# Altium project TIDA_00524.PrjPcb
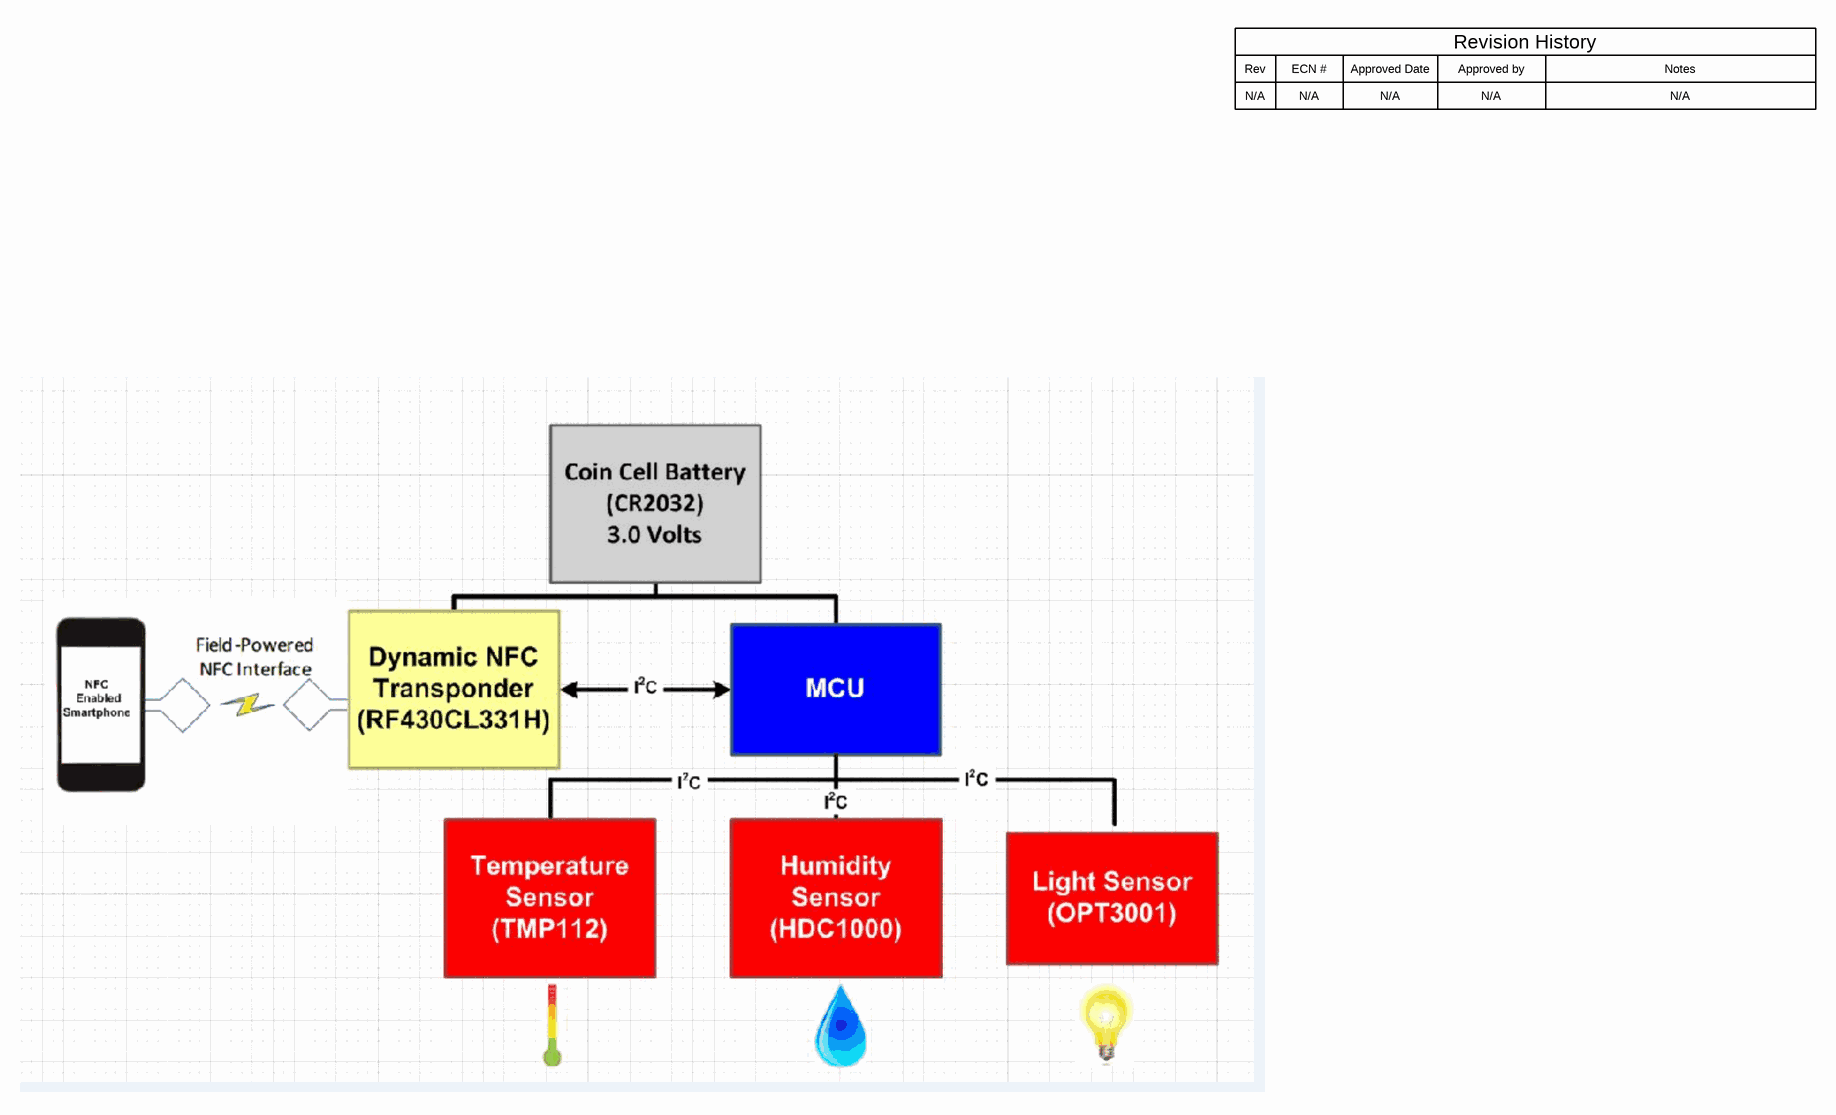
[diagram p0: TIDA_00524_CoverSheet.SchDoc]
CopyrightYear: 2015; PCB_Layout: Eddie LaCost; PCB_Rev: A; PRJ_Customer: Public Release; PRJ_Engineer: Eddie LaCost; PRJ_Number: TIDA-00524; PRJ_Title: NFC-DATALOGGER-EVM; SCH_Rev: A; TechSupport: http://www.ti.com/support; TID: TIDA-00524
3 sheets, 55 parts. Net scope: global (net labels, ports and power ports of the same name join across sheets).
Board file: TIDA00524.PcbDoc
Sheets:
  TIDA_00524_CoverSheet.SchDoc
  TIDA_00524.SchDoc
  TIDA00524_Hardware.SchDoc

## Sheet TIDA_00524_CoverSheet.SchDoc
size 431 x 279 mm; Date: Not shown in title block; ApprovedBy: Not shown in title block; CheckedBy: Not shown in title block; Author: Not shown in title block; CompanyName: Not shown in title block; Engineer: Not shown in title block; Organization: Not shown in title block; Address1: Not shown in title block; Address2: Not shown in title block; Address3: Not shown in title block; Address4: Not shown in title block; DocumentNumber: 1; Revision: Use project parameter SCH_Rev; SheetNumber: 1; SheetTotal: 3; PageSetup: Record=PageOptions¦CenterHorizontal=True¦CenterVertical=True¦PrintScale=1.00¦XCorrection=1.00¦YCorrection=1.00¦PrintKind=0¦BorderSize=5000000¦LeftOffset=0¦BottomOffset=0¦Orientation=2¦PaperLength=1000¦PaperWidth=1000¦Scale=100¦PaperSource=15¦PrintQuality=600¦MediaType=1¦DitherType=10¦PaperKind=Letter¦PrintScaleMode=1

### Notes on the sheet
- Rev
- N/A
- ECN #
- Approved Date
- Approved by
- Revision History
- Notes
- Place Block Diagram here (if appropriate) or delete this text box.
  If using a block diagram from another tool, save the picture as a .bmp file.
  Then, use menu Place|Drawing Tools|Graphic to insert the .png/.svg/.bmp file on the schematic.

## Sheet TIDA_00524.SchDoc
size 431 x 279 mm; Date: Not shown in title block; ApprovedBy: Not shown in title block; CheckedBy: Not shown in title block; Author: Not shown in title block; CompanyName: Not shown in title block; Engineer: Not shown in title block; Organization: Not shown in title block; Address1: Not shown in title block; Address2: Not shown in title block; Address3: Not shown in title block; Address4: Not shown in title block; DocumentNumber: 1; Revision: Use project parameter SCH_Rev; SheetNumber: 2; SheetTotal: 3; PageSetup: Record=PageOptions¦CenterHorizontal=True¦CenterVertical=True¦PrintScale=1.00¦XCorrection=1.00¦YCorrection=1.00¦PrintKind=0¦BorderSize=5000000¦LeftOffset=0¦BottomOffset=0¦Orientation=2¦PaperLength=1000¦PaperWidth=1000¦Scale=100¦PaperSource=15¦PrintQuality=600¦MediaType=1¦DitherType=10¦PaperKind=Letter¦PrintScaleMode=1
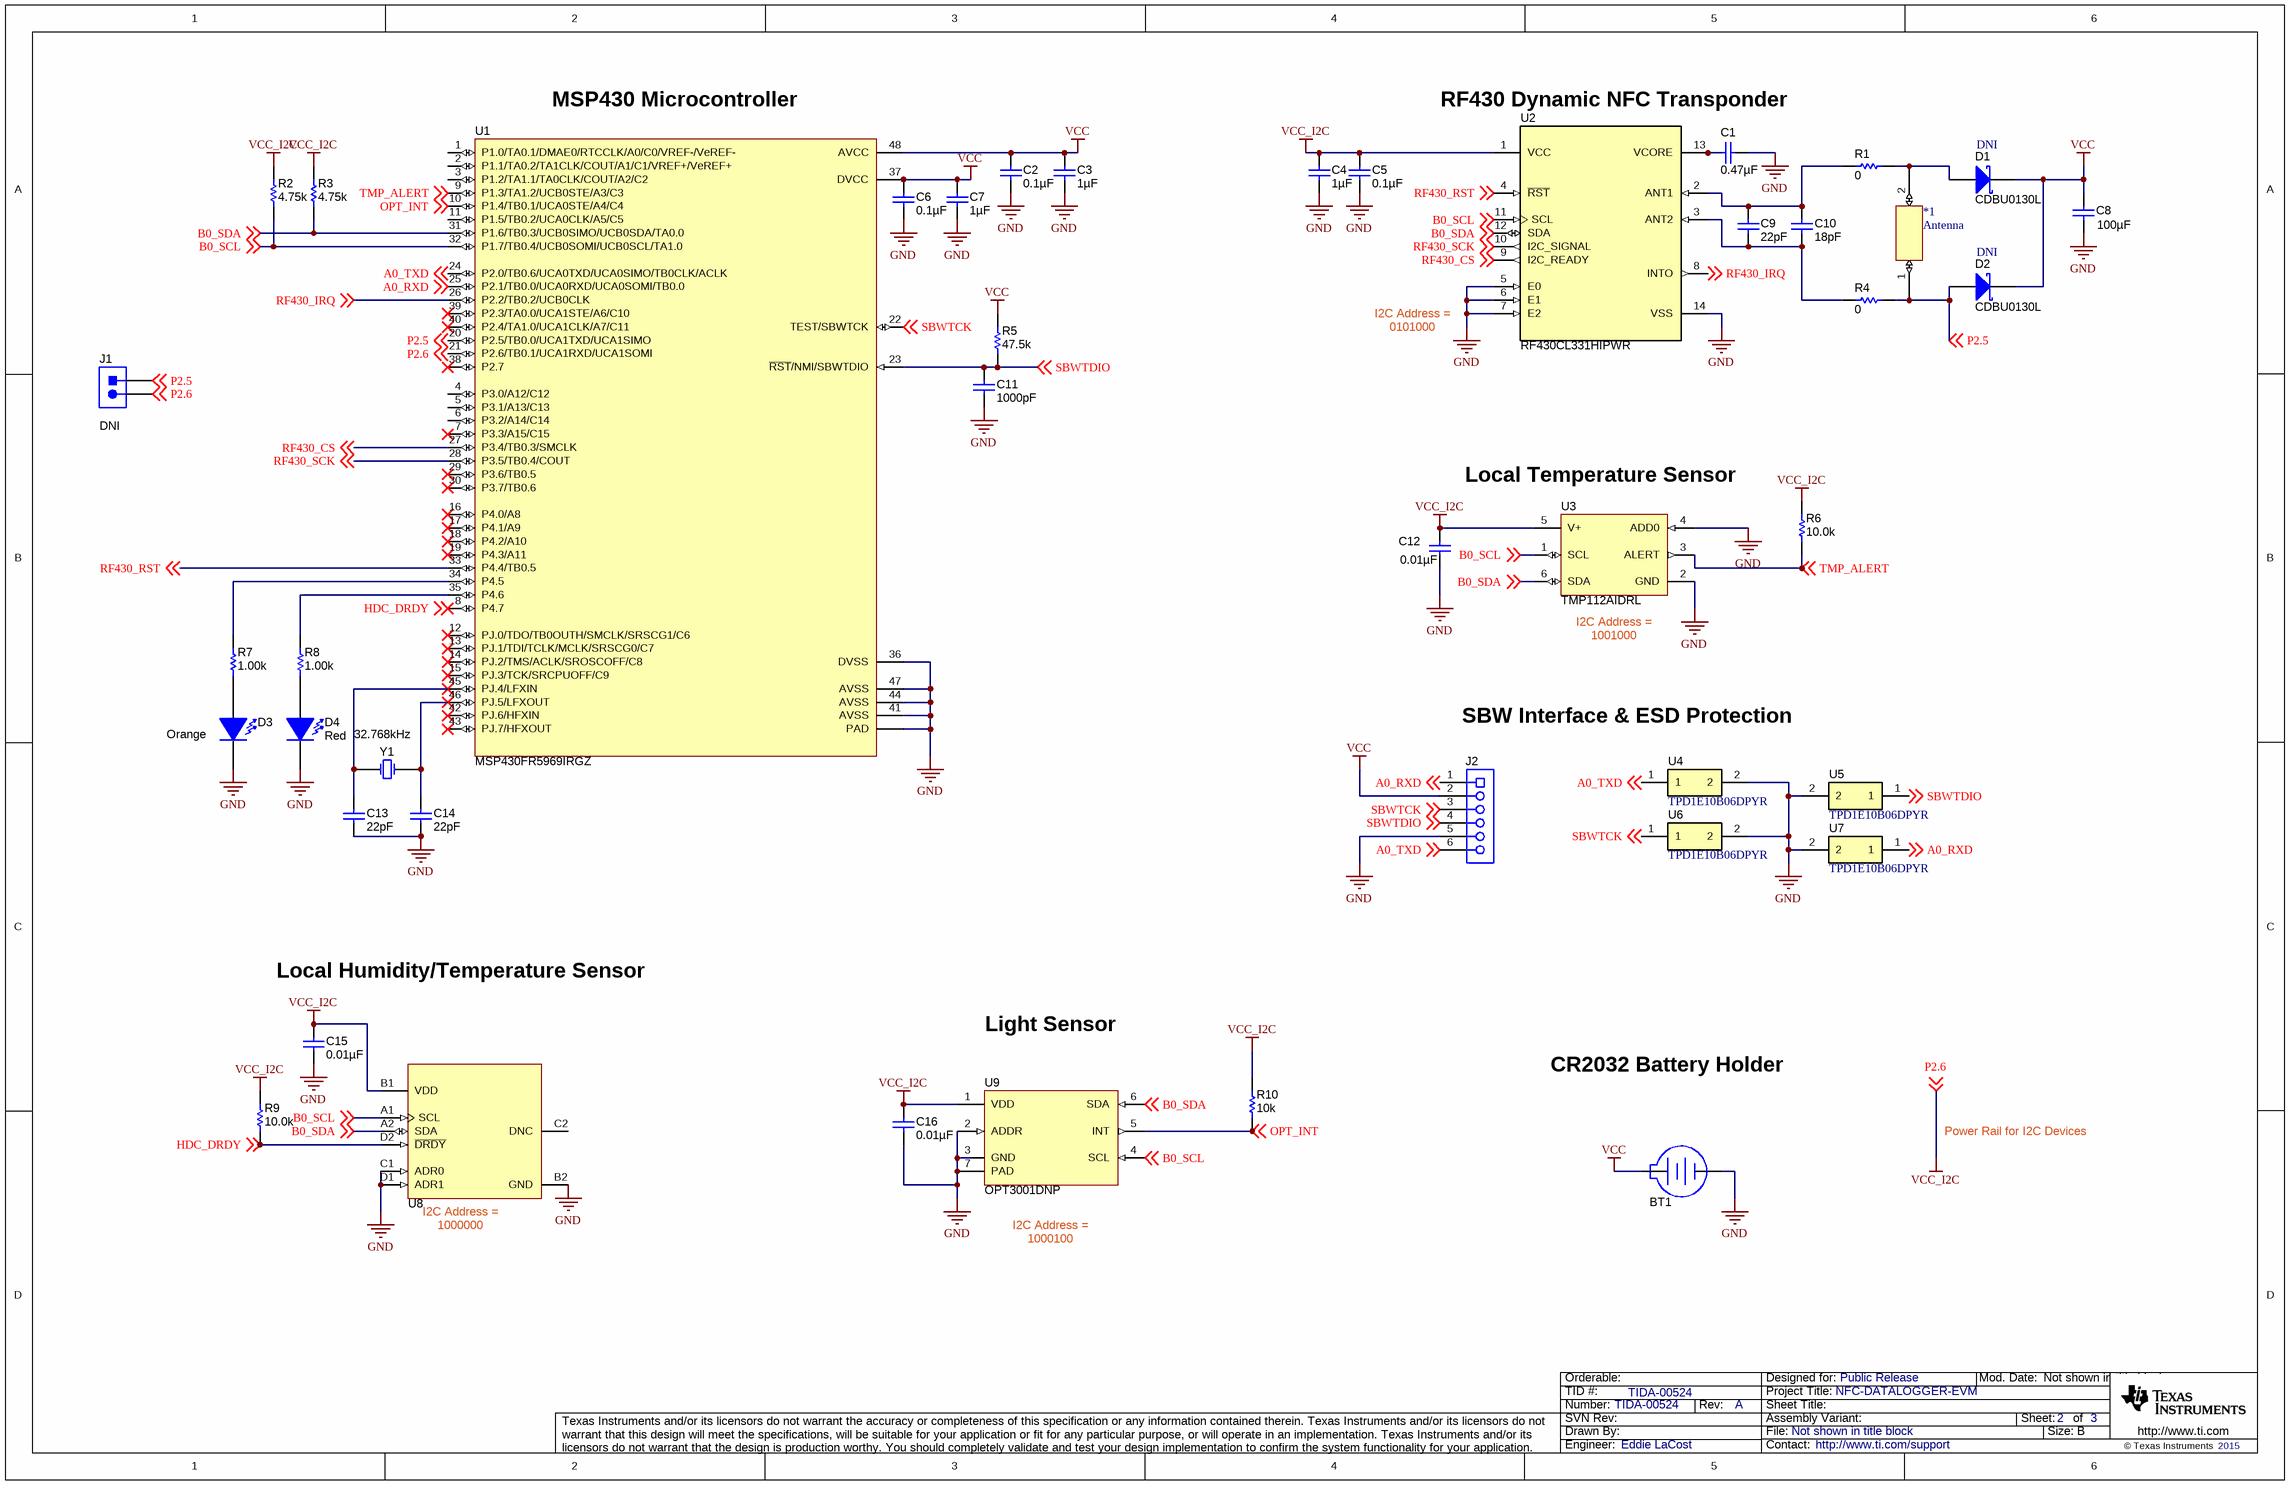
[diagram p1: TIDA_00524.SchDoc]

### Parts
*1  Antenna  [PCBComponent_1]  (no BOM)
BT1  BA2032SM  [BAT_BA2032SM]  (value not drawn)
C1  ValueDisplayed: 0.47µF  [0603]  (hidden comment: GRM188R71E474KA12D)
C2  ValueDisplayed: 0.1µF  [0402]  (hidden comment: GRM155R71C104KA88D)
C3  ValueDisplayed: 1µF  [0603]  (hidden comment: GRM188R71C105KA12D)
C4  ValueDisplayed: 1µF  [0603]  (hidden comment: GRM188R71C105KA12D)
C5  ValueDisplayed: 0.1µF  [0402]  (hidden comment: GRM155R71C104KA88D)
C6  ValueDisplayed: 0.1µF  [0402]  (hidden comment: GRM155R71C104KA88D)
C7  ValueDisplayed: 1µF  [0603]  (hidden comment: GRM188R71C105KA12D)
C8  ValueDisplayed: 100µF  [1206_190]  (hidden comment: C3216X5R1A107M160AC)
C9  ValueDisplayed: 22pF  [0402]  (hidden comment: GRM1555C1H220FA01D)
C10  ValueDisplayed: 18pF  [0402]  (hidden comment: GRM1555C1H180JA01D)
C11  ValueDisplayed: 1000pF  [0402]  (hidden comment: GRM155R71C102KA01D)
C12  ValueDisplayed: 0.01µF  [0402]  (hidden comment: GRM155R71C103KA01D)
C13  ValueDisplayed: 22pF  [0402]  (hidden comment: GRM1555C1H220FA01D)
C14  ValueDisplayed: 22pF  [0402]  (hidden comment: GRM1555C1H220FA01D)
C15  ValueDisplayed: 0.01µF  [0402]  (hidden comment: C1005X7R1E103K)
C16  ValueDisplayed: 0.01µF  [0402]  (hidden comment: 885012205031)
D1  CDBU0130L  [SOD-523F]
D2  CDBU0130L  [SOD-523F]
D3  value Orange  [SML-31_Orange]  (hidden comment: SML-311DTT86)
D4  value Red  [SML-31_Red]  (hidden comment: SML-311UTT86)
J1  GRPB021VWVN-RC  [Sullins_GRPB021VWVN-RC]  (value not drawn)
J2  851-43-006-10-001000  [Mill-Max_851-XX-006-10-001000]  (value not drawn)
R1  value 0  [0402]  (hidden comment: CRCW04020000Z0ED)
R2  value 4.75k  [0402]  (hidden comment: CRCW04024K75FKED)
R3  value 4.75k  [0402]  (hidden comment: CRCW04024K75FKED)
R4  value 0  [0402]  (hidden comment: CRCW04020000Z0ED)
R5  value 47.5k  [0402]  (hidden comment: CRCW040247K5FKED)
R6  ValueDisplayed: 10.0k  [0402]  (hidden comment: CRCW040210K0FKED)
R7  value 1.00k  [0402]  (hidden comment: CRCW04021K00FKED)
R8  value 1.00k  [0402]  (hidden comment: CRCW04021K00FKED)
R9  ValueDisplayed: 10.0k  [0402]  (hidden comment: CRCW040210K0FKED)
R10  ValueDisplayed: 10k  [0402]  (hidden comment: CRCW040210K0JNED)
U1  MSP430FR5969IRGZ  [RGZ0048B]
U2  RF430CL331HIPWR  [PW0014A_N]
U3  TMP112AIDRL  [DRL0006A]
U4  TPD1E10B06DPYR  [DPY0002A]
U5  TPD1E10B06DPYR  [DPY0002A]
U6  TPD1E10B06DPYR  [DPY0002A]
U7  TPD1E10B06DPYR  [DPY0002A]
U8  HDC1000YPAR  [YPA0008AGAE]  (value not drawn)
U9  OPT3001DNP  [DNP0006A]
Y1  Frequency: 32.768kHz  [XTAL_ABS07]  (hidden comment: ABS07-32.768KHZ-9-T)

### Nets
GND: BT1.2(-) C1.2 C2.2 C3.2 C4.2 C5.2 C6.2 C7.2 C8.2 C11.2 C12.1 C13.2 C14.2 C15.2 C16.2 D3.1(K) D4.1(K) J2.5 U1.36(DVSS) U1.41(AVSS) U1.44(AVSS) U1.47(AVSS) U1.49(PAD) U2.5(E0) U2.6(E1) U2.7(E2) U2.14(VSS) U3.2(GND) U3.4(ADD0) U4.2 U5.2 U6.2 U7.2 U8.B2(GND) U8.C1(ADR0) U8.D1(ADR1) U9.2(ADDR) U9.3(GND) U9.7(PAD)
VCC: BT1.1(+) C2.1 C3.1 C6.1 C7.1 C8.1 D1.1(K) D2.1(K) J2.2 R5.2 U1.37(DVCC) U1.48(AVCC)
VCC_I2C: C4.1 C5.1 C12.2 C15.1 C16.1 J1.2 R2.2 R3.2 R6.2 R9.1 R10.2 U1.21(P2.6/TB0.1/UCA1RXD/UCA1SOMI) U2.1(VCC) U3.5(V+) U8.B1(VDD) U9.1(VDD) ; off-sheet P2.6  [also labelled P2.6]
A0_RXD: J2.1 U1.25(P2.1/TB0.0/UCA0RXD/UCA0SOMI/TB0.0) U7.1 ; off-sheet A0_RXD
A0_TXD: J2.6 U1.24(P2.0/TB0.6/UCA0TXD/UCA0SIMO/TB0CLK/ACLK) U4.1 ; off-sheet A0_TXD
B0_SCL: R2.1 U1.32(P1.7/TB0.4/UCB0SOMI/UCB0SCL/TA1.0) U2.11(SCL) U3.1(SCL) U8.A1(SCL) U9.4(SCL) ; off-sheet B0_SCL
B0_SDA: R3.1 U1.31(P1.6/TB0.3/UCB0SIMO/UCB0SDA/TA0.0) U2.12(SDA) U3.6(SDA) U8.A2(SDA) U9.6(SDA) ; off-sheet B0_SDA
HDC_DRDY: R9.2 U1.8(P4.7) U8.D2(~{DRDY}) ; off-sheet HDC_DRDY
OPT_INT: R10.1 U1.10(P1.4/TB0.1/UCA0STE/A4/C4) U9.5(INT) ; off-sheet OPT_INT
P2.5: *1.1 D2.2(A) J1.1 R4.2 U1.20(P2.5/TB0.0/UCA1TXD/UCA1SIMO) ; off-sheet P2.5
RF430_CS: U1.27(P3.4/TB0.3/SMCLK) U2.9(I2C_READY) ; off-sheet RF430_CS
RF430_IRQ: U1.26(P2.2/TB0.2/UCB0CLK) U2.8(INTO) ; off-sheet RF430_IRQ
RF430_RST: U1.33(P4.4/TB0.5) U2.4(~{RST}) ; off-sheet RF430_RST
RF430_SCK: U1.28(P3.5/TB0.4/COUT) U2.10(I2C_SIGNAL) ; off-sheet RF430_SCK
SBWTCK: J2.3 U1.22(TEST/SBWTCK) U6.1 ; off-sheet SBWTCK
SBWTDIO: C11.1 J2.4 R5.1 U1.23(~{RST}/NMI/SBWTDIO) U5.1 ; off-sheet SBWTDIO
TMP_ALERT: R6.1 U1.9(P1.3/TA1.2/UCB0STE/A3/C3) U3.3(ALERT) ; off-sheet TMP_ALERT
Net*1_2: *1.2 D1.2(A) R1.2
NetC1_1: C1.1 U2.13(VCORE)
NetC9_1: C9.1 C10.1 R1.1 U2.2(ANT1)
NetC9_2: C9.2 C10.2 R4.1 U2.3(ANT2)
NetC13_1: C13.1 U1.45(PJ.4/LFXIN) Y1.2(OSC2)
NetC14_1: C14.1 U1.46(PJ.5/LFXOUT) Y1.1(OSC1)
NetD3_2: D3.2(A) R7.1
NetD4_2: D4.2(A) R8.1
NetR7_2: R7.2 U1.34(P4.5)
NetR8_2: R8.2 U1.35(P4.6)

Not connected (* = marked no-connect by the designer): U1 1(P1.0/TA0.1/DMAE0/RTCCLK/A0/C0/VREF-/VeREF-) 2(P1.1/TA0.2/TA1CLK/COUT/A1/C1/VREF+/VeREF+) 3(P1.2/TA1.1/TA0CLK/COUT/A2/C2) 4(P3.0/A12/C12) 5(P3.1/A13/C13) 6(P3.2/A14/C14) 7(P3.3/A15/C15)* 11(P1.5/TB0.2/UCA0CLK/A5/C5) 12(PJ.0/TDO/TB0OUTH/SMCLK/SRSCG1/C6)* 13(PJ.1/TDI/TCLK/MCLK/SRSCG0/C7)* 14(PJ.2/TMS/ACLK/SROSCOFF/C8)* 15(PJ.3/TCK/SRCPUOFF/C9)* 16(P4.0/A8)* 17(P4.1/A9)* 18(P4.2/A10)* 19(P4.3/A11)* 29(P3.6/TB0.5)* 30(P3.7/TB0.6)* 38(P2.7)* 39(P2.3/TA0.0/UCA1STE/A6/C10)* 40(P2.4/TA1.0/UCA1CLK/A7/C11)* 42(PJ.6/HFXIN)* 43(PJ.7/HFXOUT)*; U8 C2(DNC)

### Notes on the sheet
- (near U1) MSP430 Microcontroller
- RF430 Dynamic NFC Transponder
- (near D1) DNI
- (near D2) DNI
- I2C Address =
- 0101000
- Local Temperature Sensor
- (near U3) I2C Address =
- (near U3) 1001000
- SBW Interface & ESD Protection
- Local Humidity/Temperature Sensor
- Light Sensor
- CR2032 Battery Holder
- Power Rail for I2C Devices
- (near U8) I2C Address =
- (near U8) 1000000
- (near U9) I2C Address =
- 1000100

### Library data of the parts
*1 = Component_1
BT1 = BA2032SM: Battery Holder,xx 2032 series, 20mm Dia, SMT; Manufacturer: Memory Protection Devices; SymbolCreator: a0412235
C1 = GRM188R71E474KA12D: CAP, CERM, 0.47 µF, 25 V, +/- 10%, X7R, 0603; Manufacturer: MuRata; Polarized: N; CompType: Capacitor; Value: 0.47uF; U/M: EA; Cap_F: 0.00000047; Tolerance_%: 10; Value1: Unknown; VDC_V: 25; Value2: 25V; TaMin_C: -55; TaMax_C: 125; AEC Category: Q200
C2 C5 C6 = GRM155R71C104KA88D: CAP, CERM, 0.1 µF, 16 V, +/- 10%, X7R, 0402; Manufacturer: MuRata; Polarized: N; CompType: Capacitor; Value: 0.1uF; U/M: EA; Cap_F: 0.0000001; Tolerance_%: 10; Value1: Unknown; VDC_V: 16; Value2: 16V; TaMin_C: -55; TaMax_C: 125; AEC Category: Q200
C3 C4 C7 = GRM188R71C105KA12D: CAP, CERM, 1 µF, 16 V, +/- 10%, X7R, 0603; Manufacturer: MuRata; Polarized: N; CompType: Capacitor; Value: 1uF; U/M: EA; Cap_F: 0.000001; Tolerance_%: 10; ESR_ohm: 0.011; Value1: 0.011 ohm; VDC_V: 16; Value2: 16V; TaMin_C: -55; TaMax_C: 125; AEC Category: Q200
C8 = C3216X5R1A107M160AC: CAP, CERM, 100 µF, 10 V, +/- 20%, X5R, 1206_190; Manufacturer: TDK; Polarized: N; CompType: Capacitor; Value: 100uF; U/M: EA; Cap_F: 0.0001; Tolerance_%: 20; Value1: Unknown; VDC_V: 10; Value2: 10V; TaMin_C: -55; TaMax_C: 85; Cap_Case: 1206; AEC Category: Q200
C9 = GRM1555C1H220FA01D: CAP, CERM, 22 pF, 50 V, +/- 1%, C0G/NP0, 0402; Manufacturer: MuRata; Polarized: N; CompType: Capacitor; U/M: EA; Cap_F: 0.000000000022; Tolerance_%: 1; Value1: Unknown; VDC_V: 50; Value2: 50V; TaMin_C: -55; TaMax_C: 125; Value: 22pF; AEC Category: Q200
C10 = GRM1555C1H180JA01D: CAP, CERM, 18 pF, 50 V, +/- 5%, C0G/NP0, 0402; Manufacturer: MuRata; Polarized: N; CompType: Capacitor; Value: 18pF; U/M: EA; Cap_F: 0.000000000018; Tolerance_%: 5; Value1: Unknown; VDC_V: 50; Value2: 50V; TaMin_C: -55; TaMax_C: 125; AEC Category: Q200
C11 = GRM155R71C102KA01D: CAP, CERM, 1000 pF, 16 V, +/- 10%, X7R, 0402; Manufacturer: MuRata; Polarized: N; CompType: Capacitor; Value: 1000pF; U/M: EA; Cap_F: 0.000000001; Tolerance_%: 10; Value1: Unknown; VDC_V: 16; Value2: 16V; TaMin_C: -55; TaMax_C: 125; AEC Category: Q200
C12 = GRM155R71C103KA01D: CAP, CERM, 0.01 µF, 16 V, +/- 10%, X7R, 0402; Manufacturer: MuRata; Polarized: N; CompType: Capacitor; Value: 0.01uF; U/M: EA; Cap_F: 0.00000001; Tolerance_%: 10; Value1: Unknown; VDC_V: 16; Value2: 16V; TaMin_C: -55; TaMax_C: 125; AEC Category: Q200
C13 C14 = GRM1555C1H220FA01D: CAP, CERM, 22 pF, 50 V, +/- 1%, C0G/NP0, 0402; Manufacturer: MuRata; Polarized: N; CompType: Capacitor; Value: 22pF; U/M: EA; Cap_F: 0.000000000022; Tolerance_%: 1; Value1: Unknown; VDC_V: 50; Value2: 50V; TaMin_C: -55; TaMax_C: 125; AEC Category: Q200
C15 = C1005X7R1E103K: CAP, CERM, 0.01 µF, 25 V, +/- 10%, X7R, 0402; Manufacturer: TDK; Polarized: N; CompType: Capacitor; Value: 0.01uF; U/M: EA; Cap_F: 0.00000001; Tolerance_%: 10; ESR_ohm: 0.0623; Value1: 0.0623 ohm; VDC_V: 25; Value2: 25V; TaMin_C: -55; TaMax_C: 125; AEC Category: Q200
C16 = 885012205031: CAP, CERM, 0.01 µF, 16 V, +/- 10%, X7R, 0402; Manufacturer: Wurth Elektronik; Polarized: N; CompType: Capacitor; Value: 0.01uF; U/M: EA; Cap_F: 0.00000001; Tolerance_%: 10; Value1: Unknown; VDC_V: 16; Value2: 16V; TaMin_C: -55; TaMax_C: 125; AEC Category: Q200
D1 D2 = CDBU0130L: Diode, Schottky, 35 V, 0.1 A, SOD-523F; Manufacturer: Comchip Technology; U/M: EA; Value: 35V; Value1: 0.1A; Io_A: 0.1; Vr_V: 35; TJmax_C: 125; AEC Category: Q101
D3 = SML-311DTT86: LED, Orange, SMD; Manufacturer: Rohm; Type: AlInGaP; Vf_V: 1.8; Value2: 1.8V; Io_A: 0.002; Value1: W; U/M: EA
D4 = SML-311UTT86: LED, Red, SMD; Manufacturer: Rohm; Type: AlInGaP; Vf_V: 1.8; Value2: 1.8V; Io_A: 0.002; Value1: W; U/M: EA
J1 = GRPB021VWVN-RC: Header male, 2x1, 50mil, TH; Manufacturer: Sullins Connector Solutions; SymbolCreator: a0412235; U/M: EA
J2 = 851-43-006-10-001000: Receptacle, 6x1, 50mil, TH; Manufacturer: Mill-Max; SymbolCreator: a0411947; U/M: EA
R1 R4 = CRCW04020000Z0ED: RES, 0, 5%, 0.063 W, 0402; Manufacturer: Vishay-Dale; CompType: Resistor; Value_Code: 0000; Tolerance_%: 5; Power_W: 0.063; Value2: 0.063W; VDC_V: 50; TempCo: 200 ppm/C; EIA_Code: E24; U/M: EA; AEC Category: Q200
R2 R3 = CRCW04024K75FKED: RES, 4.75 k, 1%, 0.063 W, 0402; Manufacturer: Vishay-Dale; CompType: Resistor; Res_ohm: 4750; Value_Code: 4k75; Tolerance_%: 1; Power_W: 0.063; Value2: 0.063W; VDC_V: 50; TempCo: 100 ppm/C; EIA_Code: E96; U/M: EA; AEC Category: Q200
R5 = CRCW040247K5FKED: RES, 47.5 k, 1%, 0.063 W, 0402; Manufacturer: Vishay-Dale; CompType: Resistor; Res_ohm: 47500; Value_Code: 47k5; Tolerance_%: 1; Power_W: 0.063; Value2: 0.063W; VDC_V: 50; TempCo: 100 ppm/C; EIA_Code: E96; U/M: EA; AEC Category: Q200
R6 R9 = CRCW040210K0FKED: RES, 10.0 k, 1%, 0.063 W, 0402; Manufacturer: Vishay-Dale; CompType: Resistor; Value: 10.0k; U/M: EA; Res_ohm: 10000; Value_Code: 10k0; Tolerance_%: 1; Power_W: 0.063; Value2: 0.063W; VDC_V: 50; TempCo: 100 ppm/C; EIA_Code: E96; AEC Category: Q200
R7 R8 = CRCW04021K00FKED: RES, 1.00 k, 1%, 0.063 W, 0402; Manufacturer: Vishay-Dale; CompType: Resistor; Res_ohm: 1000; Value_Code: 1k00; Tolerance_%: 1; Power_W: 0.063; Value2: 0.063W; VDC_V: 50; TempCo: 100 ppm/C; EIA_Code: E96; U/M: EA; AEC Category: Q200
R10 = CRCW040210K0JNED: RES, 10 k, 5%, 0.063 W, 0402; Manufacturer: Vishay-Dale; CompType: Resistor; Value: 10k; U/M: EA; Res_ohm: 10000; Value_Code: 10k0; Tolerance_%: 5; Power_W: 0.063; Value2: 0.063W; VDC_V: 50; TempCo: 200 ppm/C; EIA_Code: E24; AEC Category: Q200
U1 = MSP430FR5969IRGZ: Mixed Signal Microcontroller, RGZ0048B; Alternate Manufacturer: None; Manufacturer: Texas Instruments; SymbolCreator: a0411947; CompType: IC; U/M: EA
U2 = RF430CL331HIPWR: NFC Type 4B Dynamic Dual Interface Transponder, PW0014A; Manufacturer: Texas Instruments; SymbolCreator: Altium; CompType: IC; U/M: EA
U3 = TMP112AIDRL: High-Accuracy, Low-Power, Digital Temperature Sensor With SMBus(TM)/Two-Wire Serial Interface, DRL0006A; Alternate Manufacturer: None; Manufacturer: Texas Instruments; SymbolCreator: a0799628; CompType: IC; U/M: EA
U4-U7 = TPD1E10B06DPYR: ESD in 0402 Package with 10 pF Capacitance and 6 V Breakdown, 1 Channel, -40 to +125 degC, 2-pin X2SON (DPY), Green (RoHS & no Sb/Br); Manufacturer: Texas Instruments; Alternate PartNumber: Equivalent; Breakdown Voltage(Min)(V): 6; Eco-Plan: TBD; IEC 61000-4-2 Air-Gap(+/- kV): 30; IO Capacitance(Typ)(pF): 10; SubFamily: ESD Solution
U8 = HDC1000YPAR: HDC1000 Low power integrated humidity and temperature Sensor, YPA0008AGAE; Alternate Manufacturer: Texas Instruments; Alternate PartNumber: HDC1000YPAT; SymbolCreator: Altium; CompType: IC; U/M: EA
U9 = OPT3001DNP: Ambient Light Sensor, DNP0006A; Alternate Manufacturer: None; Manufacturer: Texas Instruments; SymbolCreator: a0411947; CompType: IC; U/M: EA
Y1 = ABS07-32.768KHZ-9-T: CRYSTAL, 32.768KHZ, 9PF, SMD; Manufacturer: Abracon Corportation; SymbolCreator: a0412235; U/M: EA; TaMin_C: -40; TaMax_C: 85; Frequency Stability: ±20ppm

## Sheet TIDA00524_Hardware.SchDoc
size 431 x 279 mm; Date: Not shown in title block; ApprovedBy: Not shown in title block; CheckedBy: Not shown in title block; Author: Not shown in title block; CompanyName: Not shown in title block; Engineer: Not shown in title block; Organization: Not shown in title block; Address1: Not shown in title block; Address2: Not shown in title block; Address3: Not shown in title block; Address4: Not shown in title block; DocumentNumber: 1; Revision: Use project parameter SCH_Rev; SheetNumber: 3; SheetTotal: 3; PageSetup: Record=PageOptions¦CenterHorizontal=True¦CenterVertical=True¦PrintScale=1.00¦XCorrection=1.00¦YCorrection=1.00¦PrintKind=0¦BorderSize=5000000¦LeftOffset=0¦BottomOffset=0¦Orientation=2¦PaperLength=1000¦PaperWidth=1000¦Scale=100¦PaperSource=15¦PrintQuality=600¦MediaType=1¦DitherType=10¦PaperKind=Letter¦PrintScaleMode=1
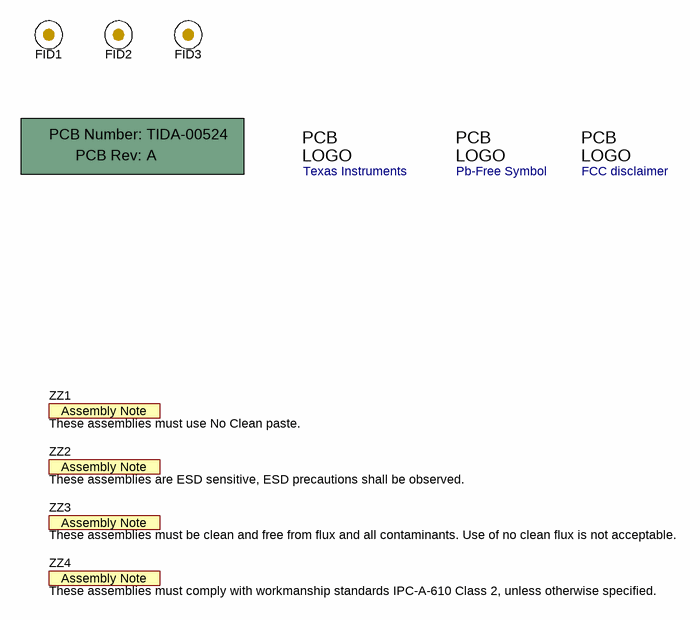
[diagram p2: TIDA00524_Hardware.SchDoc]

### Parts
!PCB1  Printed Circuit Board  (value not drawn)  (mechanical)
FID1  Fiducial  [Fiducial10-20]  (value not drawn)
FID2  Fiducial  [Fiducial10-20]  (value not drawn)
FID3  Fiducial  [Fiducial10-20]  (value not drawn)
Logo1  Texas Instruments  [TI_Stacked_Overlay_Small]  (no BOM)
Logo2  Pb-Free Symbol  [Pb-Free_Overlay_Small]  (no BOM)
Logo3  FCC disclaimer  [FCC_disclaimer]  (no BOM)
ZZ1  These assemblies must use No Clean paste.  [AssemblyNote]  (no BOM)
ZZ2  These assemblies are ESD sensitive, ESD precautions shall be observed.  [AssemblyNote]  (no BOM)
ZZ3  These assemblies must be clean and free from flux and all contaminants. Use of no clean flux is not acceptable.  [AssemblyNote]  (no BOM)
ZZ4  These assemblies must comply with workmanship standards IPC-A-610 Class 2, unless otherwise specified.  [AssemblyNote]  (no BOM)

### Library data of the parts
!PCB1 = PCB: Manufacturer: Any; PartNumber: TIDA-00524; SymbolCreator: a0412235
FID1-FID3 = Fiducial: Fiducial mark.  There is nothing to buy or mount.; SymbolCreator: codlsc
Logo1 = TI_Logo: Texas Instrument Corporate Signature; SymbolCreator: a0412235
Logo2 = Pb-Free: SymbolCreator: a0412235
Logo3 = FCC_disclaimer: SymbolCreator: codlsc
ZZ1-ZZ4 = AssemblyNote: SymbolCreator: codlsc

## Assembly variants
001: not fitted C8 D1 D2 FID1 FID2 FID3 J1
